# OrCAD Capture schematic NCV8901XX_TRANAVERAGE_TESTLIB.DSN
size A
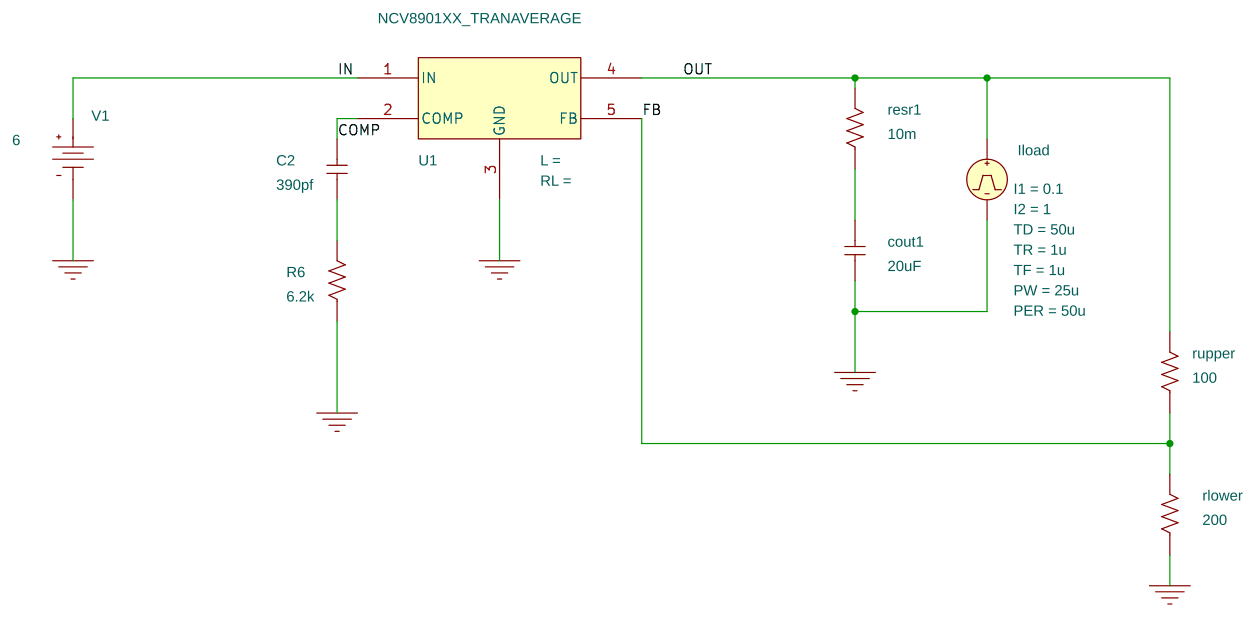
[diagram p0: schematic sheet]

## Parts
C2  390pf  [RAD/CK05]
cout1  20uF  [RAD/CK05]
Iload  IPULSE
R6  6.2k  [AX/RC05]
resr1  10m  [AX/RC05]
rlower  200  [AX/RC05]
rupper  100  [AX/RC05]
U1  NCV8901XX_TRANAVERAGE
V1  VDC

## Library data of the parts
C2 = C
cout1 = C: IC: 0
Iload = IPULSE: I1: 0.1; I2: 1; PER: 50u; PW: 25u; TD: 50u; TF: 1u; TR: 1u
R6 resr1 rlower rupper = R
U1 = NCV8901XX_TRANAVERAGE
V1 = VDC: DC: 6

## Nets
0: cout1.1 Iload.2(-) R6.1 rlower.1 U1.3(GND) V1.1(-)
COMP: C2.2 U1.2(COMP)
FB: rlower.2 rupper.1 U1.5(FB)
IN: U1.1(IN) V1.0(+)
OUT: Iload.1(+) resr1.2 rupper.2 U1.4(OUT)
N7612501: cout1.2 resr1.1
N7612533: C2.1 R6.2
